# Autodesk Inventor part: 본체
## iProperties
Company: 한국ATC센터
Created: 2014-07
Part Number: 본체
Document SubType Name: Modeling
Designer: KYOUNG IL JANG
Density: 2.71 g/cm^3
Material: 알루미늄-6061
Mass: 2881.56 g
Surface Area: 2079.92 cm^2
Volume: 1063.31 cm^3
Author: KYOUNG IL JANG
